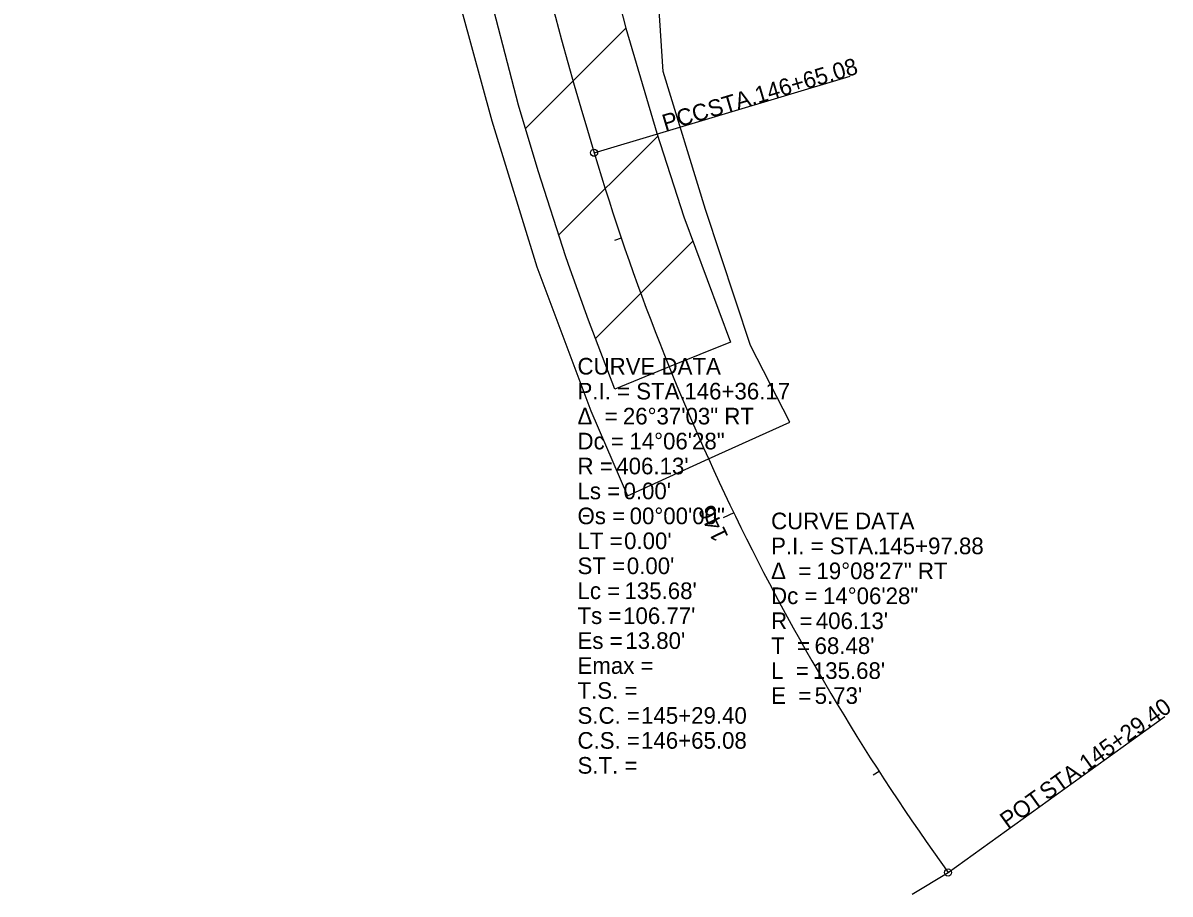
# Model space of a CAD drawing. Extents: x 195197 to 195502, y 336876 to 337459.
# Drawn here: x 195268.9 to 195462, y 336876.1 to 337022.7 of the extents above; entities that cross this region are included whole.
import ezdxf

# ---------------------------------------------------------------- set-up
doc = ezdxf.new("R2010")
doc.units = 0
for name, color, linetype in [('_CIVIL_CONSTRUCTION', 7, 'Continuous'), ('DR_P_Headwall', 7, 'Continuous'), ('DT_X_Void', 7, 'Continuous'), ('MD_P_Surface_Finished_Grade', 7, 'Continuous'), ('SC_Scratch1', 7, 'Continuous'), ('SH_Major_Grid_Line', 7, 'Continuous')]:
    doc.layers.add(name, color=color, linetype=linetype)

msp = doc.modelspace()

# ---------------------------------------------------------------- linework, layer by layer
at = {"layer": '_CIVIL_CONSTRUCTION'}
for points in [[(195287.97, 337251.38), (195291.95, 337226.7), (195292.97, 337201.54), (195292.2, 337181.16), (195292.01, 337176.07), (195280.02, 337163.48), (195272.33, 337157.95), (195268.88, 337148.33), (195288.8, 337131.36), (195292.54, 337124.96), (195302.23, 337099.91), (195307.11, 337075.58), (195321.43, 337052.24), (195341.13, 337030.76), (195347.82, 337006.27), (195355.4, 336981.71), (195364.48, 336957.43), (195370.64, 336943.15), (195384.3, 336949.34)], [(195384.3, 336949.34), (195397.97, 336955.53), (195391.34, 336968.43), (195383.81, 336991.35), (195376.66, 337014.55), (195375.01, 337039.55), (195376.79, 337065.03), (195372.56, 337089.05), (195368.12, 337112.86), (195370.07, 337138.01), (195373.6, 337153.77), (195378.92, 337164.76)]]:
    msp.add_lwpolyline(points, dxfattribs=at)
at = {"layer": 'DR_P_Headwall'}
for p, q in [((195365.03, 337000.89), (195408.15, 337013.76)), ((195369.61, 336986.53), (195368.47, 336986.14)), ((195388.54, 336940.28), (195386.74, 336939.41)), ((195424.62, 336879.7), (195461.14, 336906)), ((195413.02, 336896.72), (195412.01, 336896.07))]:
    msp.add_line(p, q, dxfattribs=at)
for centre in [(195365.03, 337000.89), (195424.62, 336879.7)]:
    msp.add_circle(centre, 0.6, dxfattribs=at)
at = {"layer": 'DT_X_Void'}
for p, q in [((195353.48, 337005), (195370.37, 337021.89)), ((195359.1, 336987.05), (195375.74, 337003.69)), ((195365.26, 336969.64), (195381.65, 336986.03))]:
    msp.add_line(p, q, dxfattribs=at)
msp.add_lwpolyline([(195365.75, 337039.78), (195370.38, 337021.87), (195375.58, 337004.19), (195380.13, 336990.1), (195387.99, 336969.02), (195377.66, 336964.85), (195368.5, 336961.06), (195364.11, 336972.68), (195360.98, 336981.27), (195360.3, 336983.37), (195355.6, 336997.84), (195352.31, 337008.93), (195346.32, 337032.1)], dxfattribs=at)
at = {"layer": 'SC_Scratch1'}
for centre, radius, start, end in [((196294.35, 337278.21), 969.82, 189.13948, 196.61598), ((195754.2, 337117.03), 406.13, 196.616, 215.7569)]:
    msp.add_arc(centre, radius, start, end, dxfattribs=at)
at = {"layer": 'SH_Major_Grid_Line'}
msp.add_line((195418.6, 336876.08), (195424.62, 336879.7), dxfattribs=at)

# ---------------------------------------------------------------- texts
at = {"layer": 'DR_P_Headwall'}
for s, rotation, p in [('146+65.08', 16.616, (195392.6, 337009.16)), (' STA. ', 16.616, (195383.67, 337006.49)), ('PCC', 16.616, (195377, 337004.5)), ('146', 115.7969, (195387.71, 336936.27)), ('145+29.40', 35.7569, (195448.02, 336896.59)), (' STA. ', 35.7569, (195440.45, 336891.14)), ('POT', 35.7569, (195434.66, 336886.98))]:
    msp.add_text(s, height=2.8, rotation=rotation, dxfattribs=at).set_placement(p)
at = {"layer": 'MD_P_Surface_Finished_Grade'}
for s, p in [('CURVE DATA', (195362.24, 336963.55)), ('P.I. = STA. ', (195362.24, 336959.35)), ('146+36.17', (195380.23, 336959.35)), ('Δ  = ', (195362.24, 336955.15)), ('26°37\'03" RT', (195369.88, 336955.15)), ('Dc = ', (195362.24, 336950.95)), ('14°06\'28"', (195370.98, 336950.95)), ('R = ', (195362.24, 336946.75)), ("406.13'", (195368.77, 336946.75)), ('Ls = ', (195362.24, 336942.55)), ("0.00'", (195369.98, 336942.55)), ('Θs = ', (195362.24, 336938.35)), ('00°00\'00"', (195371.02, 336938.35)), ('CURVE DATA', (195394.83, 336937.5)), ('LT = ', (195362.24, 336934.15)), ("0.00'", (195370.08, 336934.15)), ('P.I. = STA. ', (195394.83, 336933.3)), ('145+97.88', (195412.82, 336933.3)), ('ST = ', (195362.24, 336929.95)), ("0.00'", (195370.54, 336929.95)), ('Δ  = ', (195394.83, 336929.1)), ('19°08\'27" RT', (195402.47, 336929.1)), ('Lc = ', (195362.24, 336925.75)), ("135.68'", (195370.15, 336925.75)), ('Dc = ', (195394.83, 336924.9)), ('14°06\'28"', (195403.57, 336924.9)), ('Ts = ', (195362.24, 336921.55)), ("106.77'", (195369.92, 336921.55)), ('R  = ', (195394.83, 336920.7)), ("406.13'", (195402.36, 336920.7)), ('Es = ', (195362.24, 336917.35)), ("13.80'", (195370.29, 336917.35)), ('T  = ', (195394.83, 336916.5)), ("68.48'", (195402.15, 336916.5)), ('Emax = ', (195362.24, 336913.15)), ('L  = ', (195394.83, 336912.3)), ("135.68'", (195401.86, 336912.3)), ('T.S. = ', (195362.24, 336908.95)), ('E  = ', (195394.83, 336908.1)), ("5.73'", (195402.17, 336908.1)), ('S.C. = ', (195362.24, 336904.75)), ('145+29.40', (195372.94, 336904.75)), ('C.S. = ', (195362.24, 336900.55)), ('146+65.08', (195372.94, 336900.55)), ('S.T. = ', (195362.24, 336896.35))]:
    msp.add_text(s, height=2.8, dxfattribs=at).set_placement(p)

doc.saveas('drawing.dxf')
